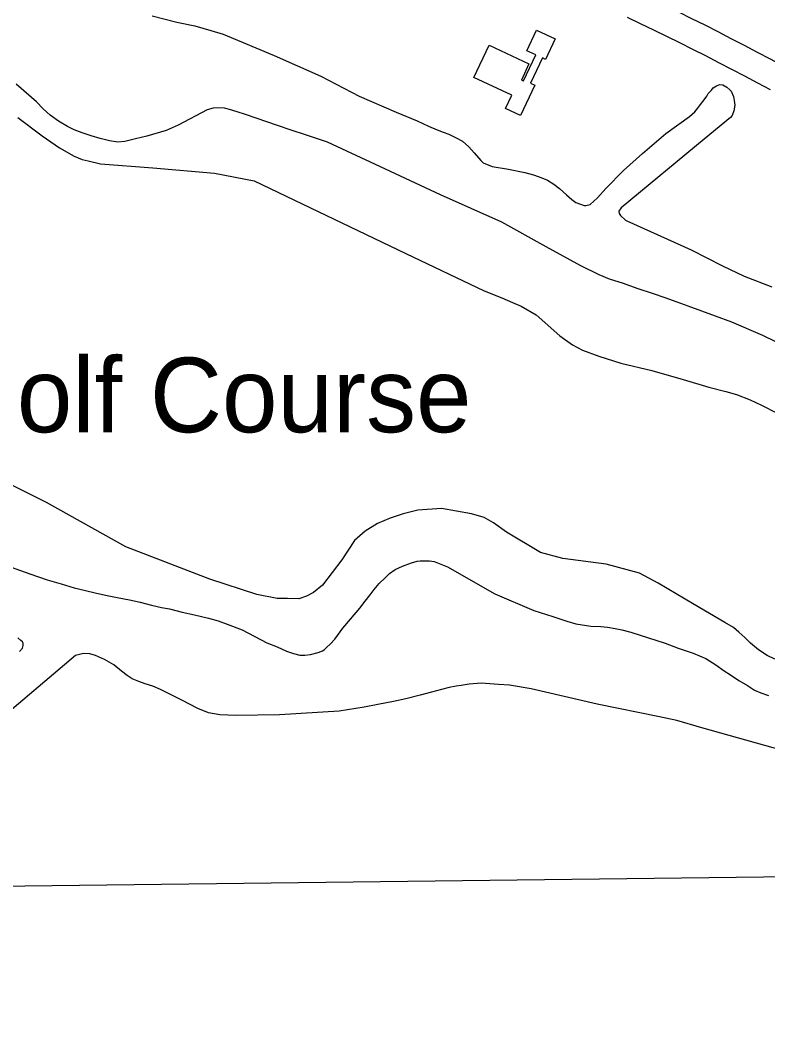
# Model space of a CAD drawing. Extents: x 3704301 to 3742427, y 506229 to 532009.
# Drawn here: x 3721471 to 3722303, y 511646 to 512767 of the extents above; entities that cross this region are included whole.
import ezdxf

# ---------------------------------------------------------------- set-up
doc = ezdxf.new("R2010")
doc.units = 0
for name, color, linetype in [('V-BLDG-IDEN', 7, 'Continuous'), ('V-BLDG-OTLN', 7, 'Continuous'), ('V-GRID-FRAM', 7, 'Continuous'), ('V-ROAD-CNTR', 7, 'Continuous'), ('V-SITE-OTLN', 7, 'Continuous'), ('V-TOPO-SHOR', 7, 'Continuous')]:
    doc.layers.add(name, color=color, linetype=linetype)

msp = doc.modelspace()

# ---------------------------------------------------------------- linework, layer by layer
at = {"layer": 'V-BLDG-OTLN'}
msp.add_lwpolyline([(3722034.2, 512733.3), (3722045, 512756.2), (3722065.9, 512746.5), (3722055.3, 512723.6), (3722051.8, 512725.2), (3722038.6, 512697.1), (3722043.1, 512695), (3722027.3, 512661.3), (3722010.7, 512669), (3722017.6, 512683.8), (3721975.5, 512703.4), (3721992.4, 512739.4), (3722036.7, 512718.7), (3722028.3, 512700.7), (3722030.8, 512699.6), (3722044.3, 512728.6)], close=True, dxfattribs=at)
at = {"layer": 'V-GRID-FRAM'}
msp.add_lwpolyline([(3708355.7, 529827.8), (3740022.4, 530214.7), (3740252.5, 512033.3), (3708569.9, 511646.2), (3708355.7, 529827.8)], dxfattribs=at)
at = {"layer": 'V-ROAD-CNTR'}
for points in [[(3722091.4, 512828.8), (3722114.1, 512818.5), (3722129, 512811.7), (3722143.9, 512804.8), (3722158.7, 512797.8), (3722173.5, 512790.8), (3722188.3, 512783.7), (3722203, 512776.5), (3722217.7, 512769.2), (3722232.3, 512761.9), (3722247, 512754.5), (3722261.5, 512747), (3722276.1, 512739.5), (3722290.6, 512731.8), (3722305, 512724.2), (3722331.8, 512709.8)], [(3722145.9, 512770.7), (3722160.6, 512763.7), (3722175.2, 512756.7), (3722189.8, 512749.6), (3722204.3, 512742.4), (3722218.8, 512735.1), (3722233.3, 512727.8), (3722247.8, 512720.3), (3722262.2, 512712.9), (3722276.6, 512705.3), (3722290.9, 512697.7), (3722305.2, 512690)]]:
    msp.add_lwpolyline(points, dxfattribs=at)
at = {"layer": 'V-SITE-OTLN'}
for points in [[(3721467.9, 512659.1), (3721495.2, 512638.6), (3721514.4, 512625.1), (3721530.6, 512616), (3721539.7, 512612.3), (3721546.4, 512610.7), (3721559.8, 512607.3), (3721618.3, 512603.1), (3721686.9, 512597.1), (3721731, 512588.4), (3721899.6, 512507.5), (3721986.7, 512466.1), (3722006.5, 512458.2), (3722018.3, 512453.2), (3722028.1, 512449.1), (3722044.6, 512439.4), (3722071.1, 512416.1), (3722085.2, 512405.9), (3722096.3, 512400.2), (3722114.6, 512393.4), (3722138.8, 512385.8), (3722173.6, 512377.4), (3722208.4, 512367.4), (3722237, 512359), (3722255.8, 512354.2), (3722267.6, 512350.8), (3722282.8, 512344.8), (3722295.4, 512338.8), (3722312.9, 512330.2)], [(3721939.5, 512224), (3721913.2, 512222.3), (3721896.9, 512218), (3721882.2, 512213.2), (3721868.2, 512207.3), (3721854.5, 512198.9), (3721842.5, 512188.3), (3721828.5, 512167), (3721806.9, 512138.7), (3721797.1, 512130.5), (3721789.1, 512126.4), (3721780.5, 512123.6), (3721767.9, 512123.7), (3721756.5, 512124), (3721733.9, 512128.2), (3721681.6, 512145.5), (3721588.3, 512181.4), (3721499.8, 512230.6), (3721370.1, 512295.5)], [(3722310.3, 512056.4), (3722301.8, 512060.3), (3722292.2, 512066.8), (3722283.3, 512074.1), (3722276.8, 512080.3), (3722270.4, 512086.3), (3722264.2, 512091.5), (3722254.5, 512097.2), (3722220.5, 512117.3), (3722180.6, 512140.9), (3722159.8, 512151.9), (3722122.7, 512162.1), (3722074.4, 512168.3), (3722049.4, 512175.2), (3722011.6, 512197.5), (3721997.2, 512208.2), (3721986.7, 512213.9), (3721972.8, 512218.1), (3721939.5, 512224)]]:
    msp.add_lwpolyline(points, dxfattribs=at)
at = {"layer": 'V-TOPO-SHOR'}
for points in [[(3721617.4, 512772.1), (3721645.1, 512765), (3721665.1, 512760.8), (3721682.9, 512755.6), (3721696.5, 512751.6), (3721753.2, 512728), (3721805.3, 512705.1), (3721847.9, 512682.7), (3721889, 512664.8), (3721912.3, 512655.1), (3721924.9, 512649.4), (3721934.6, 512645.2), (3721941.1, 512642.6), (3721947.5, 512640.5), (3721955.7, 512636.4), (3721962.6, 512632.5), (3721969.8, 512626.3), (3721975.7, 512619.6), (3721983.1, 512611.3), (3721985.9, 512608.5), (3721995.7, 512604.5), (3722013.9, 512601.4), (3722032.1, 512597.7), (3722041.6, 512595.1), (3722051.1, 512591.9), (3722057.3, 512589.1), (3722064.5, 512584.9), (3722070.6, 512580), (3722078.6, 512573), (3722084.5, 512567.8), (3722088.8, 512564.5), (3722094, 512562.4), (3722098.1, 512561.1), (3722100.1, 512561.1), (3722104.8, 512562.3), (3722113, 512569.7), (3722122.3, 512580), (3722142, 512599.9), (3722163.2, 512618.9), (3722189, 512641.1)], [(3722325.2, 512402.8), (3722296.9, 512416.5), (3722262.3, 512431.1), (3722244.3, 512437.9), (3722229.2, 512443.4), (3722214, 512448.9), (3722201.7, 512453.5), (3722188.1, 512458.2), (3722175.2, 512462.7), (3722157, 512468.9), (3722142.1, 512474.2), (3722126.2, 512479.1), (3722114.9, 512484.1), (3722094.4, 512494), (3722055.9, 512515.2), (3722006.7, 512542.5), (3721938.4, 512572.9), (3721866, 512606.7), (3721812.4, 512631.5), (3721788, 512639.8), (3721772.1, 512645), (3721756.9, 512650), (3721745.1, 512654.2), (3721733.3, 512658.3), (3721721.5, 512662.3), (3721712.2, 512665.4), (3721703.5, 512668), (3721697.9, 512669.3), (3721690.4, 512669.9), (3721685.3, 512669.4), (3721678.6, 512667.4), (3721646.3, 512650.3), (3721633.2, 512644.4), (3721611.5, 512638.1), (3721598.9, 512635.1), (3721587.1, 512632.3), (3721579.1, 512631.6), (3721570.1, 512632.9), (3721559.6, 512635.6), (3721549.5, 512638.7), (3721539.5, 512641.8), (3721530.8, 512645.2), (3721523.1, 512648.9), (3721513.4, 512654.8), (3721503.9, 512661.6), (3721496.2, 512668.5), (3721488.8, 512676.3), (3721466, 512696)], [(3722189, 512641.1), (3722215.3, 512660), (3722221.3, 512665.4), (3722224.4, 512669), (3722227.5, 512673.3), (3722231.6, 512678.7), (3722234.8, 512682.8), (3722236.3, 512685.6), (3722239.7, 512689.5), (3722241.7, 512692), (3722245.4, 512694.3), (3722249, 512695.6), (3722252.6, 512695.3), (3722256.9, 512692.7), (3722260.2, 512689.9), (3722261.9, 512688.3), (3722264.3, 512682.4), (3722265.1, 512677.8), (3722265.8, 512672.6), (3722264.8, 512666.5), (3722262.9, 512661.3), (3722261.1, 512659), (3722231.7, 512635), (3722139.2, 512558.3), (3722136.9, 512554.7), (3722137.1, 512552.1), (3722138.4, 512549.8), (3722144, 512544.6), (3722145.6, 512543.9), (3722217.2, 512511.6), (3722252.1, 512493.9), (3722276.2, 512482.5), (3722307, 512470.5)], [(3721460.7, 512158.7), (3721481.2, 512151.4), (3721500.7, 512144.8), (3721516.2, 512140.1), (3721530.5, 512135.9), (3721541.8, 512133.3), (3721555.7, 512129.9), (3721567.3, 512127.3), (3721578.6, 512125.1), (3721592.2, 512122.2), (3721604.3, 512119.6), (3721616.6, 512116.5), (3721627.7, 512113.8), (3721636.7, 512112.2), (3721650.8, 512108.6), (3721664.4, 512105.7), (3721680.1, 512102), (3721690.9, 512099.1), (3721701.1, 512095.2), (3721717.6, 512088.9), (3721745, 512074.7), (3721756.6, 512070), (3721766.8, 512065.3), (3721774.8, 512062.7), (3721781.7, 512060.8), (3721787.4, 512060.8), (3721793.8, 512061.5), (3721802.3, 512063.6), (3721807, 512065.6), (3721809, 512066.9), (3721811.6, 512069.4), (3721815.5, 512073), (3721820.9, 512078.6), (3721829.7, 512090.7), (3721838, 512100.7), (3721848.6, 512113), (3721854.6, 512120.7), (3721860, 512128.1), (3721864.4, 512133.7), (3721870.1, 512140.4), (3721876.6, 512146.8), (3721881.5, 512151.6), (3721887.9, 512156.2), (3721896.2, 512159.8), (3721906, 512163.6), (3721912.4, 512165.4), (3721915.5, 512165.9), (3721926, 512165.6), (3721931.4, 512165), (3721946.1, 512159), (3721998.9, 512129.2), (3722042, 512110.4), (3722063.3, 512103.7), (3722079, 512098.7)], [(3722079, 512098.7), (3722089, 512095.5), (3722105.7, 512093.1), (3722116.8, 512092.8), (3722124.2, 512092), (3722132.7, 512090.4), (3722139.9, 512089.1), (3722150.2, 512086.5), (3722188.2, 512074.2), (3722202.6, 512068.5), (3722219.3, 512063), (3722233.4, 512057), (3722244.7, 512050), (3722253.9, 512043.3), (3722261.1, 512038.9), (3722270.3, 512032.6), (3722279.8, 512026.9), (3722287.5, 512022), (3722294.7, 512018.9), (3722303.4, 512015.8)], [(3721470, 512065), (3721473.1, 512068.6), (3721474.1, 512071.7), (3721473.9, 512074.2), (3721473.1, 512075.8), (3721471.3, 512077.3), (3721468, 512080.2)], [(3721759.3, 511994.3), (3721710.6, 511993.5), (3721692.9, 511994.4), (3721680.3, 511996.8), (3721668.2, 512001.5), (3721650.5, 512010.6), (3721626.9, 512022.5), (3721618.2, 512026.2), (3721609.5, 512029), (3721602.5, 512031.4), (3721595.4, 512034.3), (3721589.7, 512038.1), (3721583.3, 512043.1), (3721574.9, 512050), (3721564.6, 512055.8), (3721554.3, 512060.4), (3721548.2, 512062.3), (3721541, 512062.8), (3721532.2, 512060.3), (3721456.5, 511996.1)], [(3722317.8, 511955), (3722299, 511960.2), (3722229.1, 511979.9), (3722201.1, 511988), (3722181.9, 511992.2), (3722112.5, 512006.2), (3722039, 512023.5), (3722015.1, 512027.5), (3722002.8, 512028.3), (3721983.7, 512029.7), (3721970.1, 512028.5), (3721961.4, 512027), (3721955.7, 512026.3), (3721948, 512024.8), (3721939.5, 512022.7), (3721928.1, 512019.7), (3721915.8, 512016.4), (3721899.8, 512012.1), (3721885.9, 512009.4), (3721868.6, 512005.9), (3721853.5, 512002.9), (3721825.6, 511998.6), (3721759.3, 511994.3)]]:
    msp.add_lwpolyline(points, dxfattribs=at)

# ---------------------------------------------------------------- texts
at = {"layer": 'V-BLDG-IDEN'}
msp.add_text('Golf Course', height=83, dxfattribs=at).set_placement((3721380.6, 512308.8))

doc.saveas('drawing.dxf')
